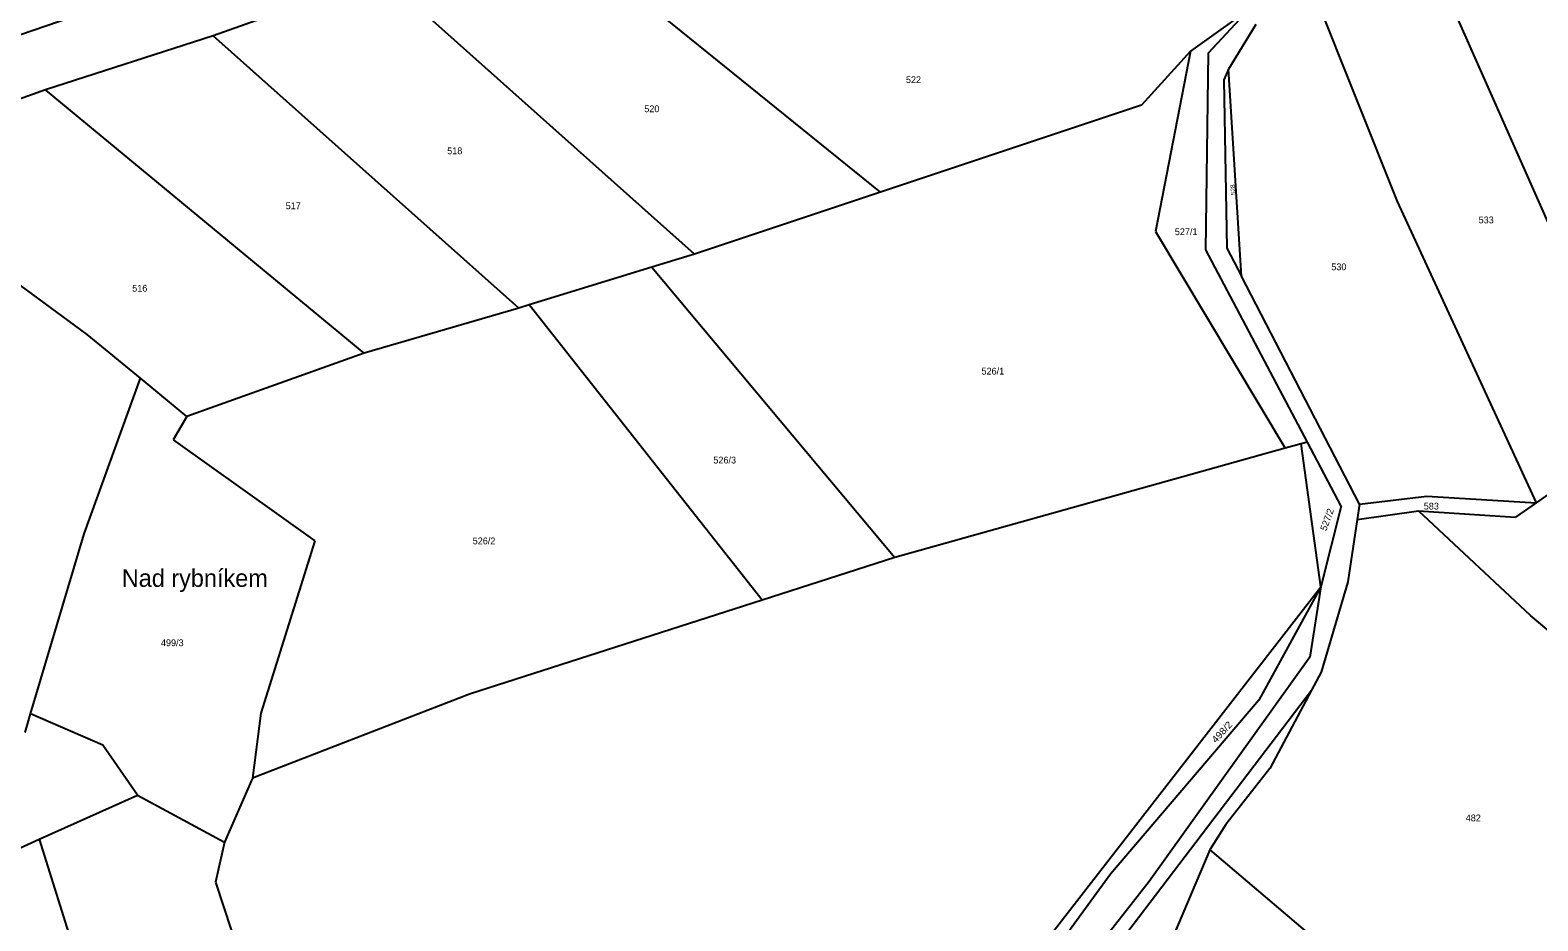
# Model space of a CAD drawing. Extents: x -664548 to -662415, y -1069720 to -1068208.
# Drawn here: x -664249.9 to -663871.7, y -1069341.5 to -1069118.2 of the extents above; entities that cross this region are included whole.
import ezdxf
from ezdxf.enums import TextEntityAlignment as Align

# ---------------------------------------------------------------- set-up
doc = ezdxf.new("R2010")
doc.units = 0
doc.header["$LTSCALE"] = 0.68
doc.layers.add('1', color=7, linetype='Continuous', lineweight=25)
doc.layers.add('7', color=7, linetype='Continuous', lineweight=13)
doc.layers.add('2', color=7, linetype='Continuous')

msp = doc.modelspace()

# ---------------------------------------------------------------- linework, layer by layer
at = {"layer": '1'}
for p, q in [((-664347.85, -1069152.04), (-664169.52, -1069090.79)), ((-663899.9, -1069096.97), (-663868.16, -1069168.67)), ((-664161.56, -1069104.5), (-664204.03, -1069119.58)), ((-664083.22, -1069174.31), (-664161.56, -1069104.5)), ((-664036.58, -1069158.78), (-664105.73, -1069102.94)), ((-663927.9, -1069108.67), (-663906.99, -1069161.11)), ((-663944.16, -1069113), (-663958.84, -1069123.44)), ((-663954.29, -1069123.88), (-663944.16, -1069113)), ((-663942.44, -1069116.73), (-663949.33, -1069127.94)), ((-664204.03, -1069119.58), (-664246.07, -1069133.11)), ((-664127.3, -1069187.87), (-664204.03, -1069119.58)), ((-663958.84, -1069123.44), (-663971.13, -1069136.98)), ((-663958.84, -1069123.44), (-663967.61, -1069168.68)), ((-663955.01, -1069173.22), (-663954.29, -1069123.88)), ((-663949.33, -1069127.94), (-663950.49, -1069130.62)), ((-663946.05, -1069179.85), (-663949.33, -1069127.94)), ((-663950.49, -1069130.62), (-663949.7, -1069172.8)), ((-664246.07, -1069133.11), (-664256.09, -1069136.68)), ((-664166.08, -1069199.16), (-664246.07, -1069133.11)), ((-663971.13, -1069136.98), (-664036.58, -1069158.78)), ((-664036.58, -1069158.78), (-664083.22, -1069174.31)), ((-663906.99, -1069161.11), (-663872.12, -1069236.66)), ((-663967.61, -1069168.68), (-663935.05, -1069223.01)), ((-664235.59, -1069194.44), (-664265.08, -1069172.85)), ((-663929.5, -1069221.46), (-663955.01, -1069173.22)), ((-663949.7, -1069172.8), (-663946.05, -1069179.85)), ((-664093.95, -1069177.61), (-664124.71, -1069187.07)), ((-664083.22, -1069174.31), (-664093.95, -1069177.61)), ((-664093.95, -1069177.61), (-664033, -1069250.41)), ((-663916.44, -1069237.06), (-663946.05, -1069179.85)), ((-664127.3, -1069187.87), (-664166.08, -1069199.16)), ((-664124.71, -1069187.07), (-664127.3, -1069187.87)), ((-664066.25, -1069261.09), (-664124.71, -1069187.07)), ((-664222.23, -1069205.44), (-664235.59, -1069194.44)), ((-664166.08, -1069199.16), (-664210.6, -1069215.02)), ((-664236.34, -1069244.43), (-664222.23, -1069205.44)), ((-664210.6, -1069215.02), (-664222.23, -1069205.44)), ((-664210.6, -1069215.02), (-664214.01, -1069220.93)), ((-663843.03, -1069216.25), (-663872.12, -1069236.66)), ((-664214.01, -1069220.93), (-664178.46, -1069246.22)), ((-663931.07, -1069221.9), (-663935.05, -1069223.01)), ((-663929.5, -1069221.46), (-663931.07, -1069221.9)), ((-663926.13, -1069257.72), (-663931.07, -1069221.9)), ((-663921.02, -1069237.51), (-663929.5, -1069221.46)), ((-663921.02, -1069237.51), (-663926.13, -1069257.72)), ((-663916.44, -1069237.06), (-663917, -1069240.83)), ((-663916.44, -1069237.06), (-663899.54, -1069235.05)), ((-663899.54, -1069235.05), (-663872.12, -1069236.66)), ((-663872.12, -1069236.66), (-663877.26, -1069240.26)), ((-663917, -1069240.83), (-663901.62, -1069238.7)), ((-663873.52, -1069264.98), (-663901.62, -1069238.7)), ((-663901.62, -1069238.7), (-663877.26, -1069240.26)), ((-664249.82, -1069289.64), (-664236.34, -1069244.43)), ((-664178.46, -1069246.22), (-664192, -1069289.42)), ((-663926.13, -1069257.72), (-663941.7, -1069286.18)), ((-663926.13, -1069257.72), (-663928.91, -1069275.4)), ((-664066.25, -1069261.09), (-664139.68, -1069284.67)), ((-663846.2, -1069287.9), (-663873.52, -1069264.98)), ((-663928.91, -1069275.4), (-663969.18, -1069331.66)), ((-663926.05, -1069279.12), (-663928.47, -1069283.68)), ((-664139.68, -1069284.67), (-664194.16, -1069305.73)), ((-664012.33, -1069393.77), (-663928.47, -1069283.68)), ((-663941.7, -1069286.18), (-663978.86, -1069329.77)), ((-663928.47, -1069283.68), (-663938.88, -1069303.31)), ((-664251.2, -1069294.26), (-664249.82, -1069289.64)), ((-664231.67, -1069297.45), (-664249.82, -1069289.64)), ((-664192, -1069289.42), (-664194.16, -1069305.73)), ((-664222.96, -1069309.98), (-664231.67, -1069297.45)), ((-664194.16, -1069305.73), (-664201.17, -1069321.78)), ((-663938.88, -1069303.31), (-663949.96, -1069317.33)), ((-664247.65, -1069321.07), (-664222.96, -1069309.98)), ((-664222.96, -1069309.98), (-664201.17, -1069321.78)), ((-663949.96, -1069317.33), (-663953.93, -1069323.72)), ((-664284.13, -1069337.46), (-664247.65, -1069321.07)), ((-664247.65, -1069321.07), (-664192.8, -1069496)), ((-664201.17, -1069321.78), (-664203.39, -1069331.82)), ((-663953.93, -1069323.72), (-663964.29, -1069347.98)), ((-663953.93, -1069323.72), (-663918.34, -1069353.91)), ((-664203.39, -1069331.82), (-664193.07, -1069363.25)), ((-663969.18, -1069331.66), (-664015.79, -1069390.96)), ((-663978.86, -1069329.77), (-663999.13, -1069357.49))]:
    msp.add_line(p, q, dxfattribs=at)
for points in [[(-663935.05, -1069223.01), (-664033, -1069250.41), (-664066.25, -1069261.09)], [(-663917, -1069240.83), (-663919.32, -1069256.48), (-663926.05, -1069279.12)], [(-664019.73, -1069379.75), (-664004.55, -1069358.75), (-663926.13, -1069257.72)]]:
    msp.add_lwpolyline(points, dxfattribs=at)

# ---------------------------------------------------------------- texts
at = {"layer": '2'}
for s, p in [('522', (-664030.21, -1069131.425)), ('520', (-664095.85, -1069138.725)), ('518', (-664145.29, -1069149.265)), ('517', (-664185.81, -1069163.045)), ('533', (-663886.54, -1069166.594)), ('527/1', (-663962.76, -1069169.554)), ('530', (-663923.5, -1069178.354)), ('516', (-664224.31, -1069183.725)), ('526/1', (-664011.25, -1069204.515)), ('526/3', (-664078.51, -1069226.814)), ('583', (-663900.3, -1069238.354)), ('526/2', (-664138.89, -1069247.084)), ('499/3', (-664217.1, -1069272.625)), ('482', (-663889.78, -1069316.554))]:
    msp.add_text(s, height=1.7, dxfattribs=at).set_placement(p)
for s, height, rotation, p in [('528', 1.14, 95, (-663947.506, -1069159.425)), ('527/2', 1.7, 70, (-663924.75, -1069243.855))]:
    msp.add_text(s, height=height, rotation=rotation, dxfattribs=at).set_placement(p)
at = {"layer": '2', "width": 1.1}
msp.add_text('498/2', height=1.7, rotation=47, dxfattribs=at).set_placement((-663952.449, -1069297.029))
at = {"layer": '7'}
msp.add_text('Nad rybníkem', height=4.4, dxfattribs=at).set_placement((-664208.609, -1069257.76), align=Align.CENTER)

doc.saveas('drawing.dxf')
